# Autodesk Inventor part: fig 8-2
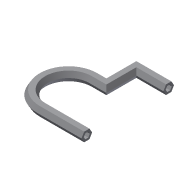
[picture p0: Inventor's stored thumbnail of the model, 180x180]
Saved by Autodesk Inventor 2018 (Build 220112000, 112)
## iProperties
Created: 2004-05
Part Number: fig 8-2
Document SubType Name: Modeling
Designer: CADCIM Technologies
Manufacturer: Standard
Standards Organization: Custom
Density: 1 g/cm^3
Material: Generic
Appearance: Default
Author: CADCIM Technologies
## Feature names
1. Sweep4
## Parameters: d3 = 0, d4 = 0
